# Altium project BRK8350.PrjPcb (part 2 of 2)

## Sheet Transceiver-M2.SchDoc: BRK8350 - M.2
size C; Author: Casey Smith; Organization: Opal Kelly; Address1: 13500 SW 72nd Ave STE 100; Address2: Portland, OR 97223; Address3: 217.391.3724; Address4: http://www.opalkelly.com; DocumentNumber: 6; Revision: 1; SheetNumber: 6; SheetTotal: 7
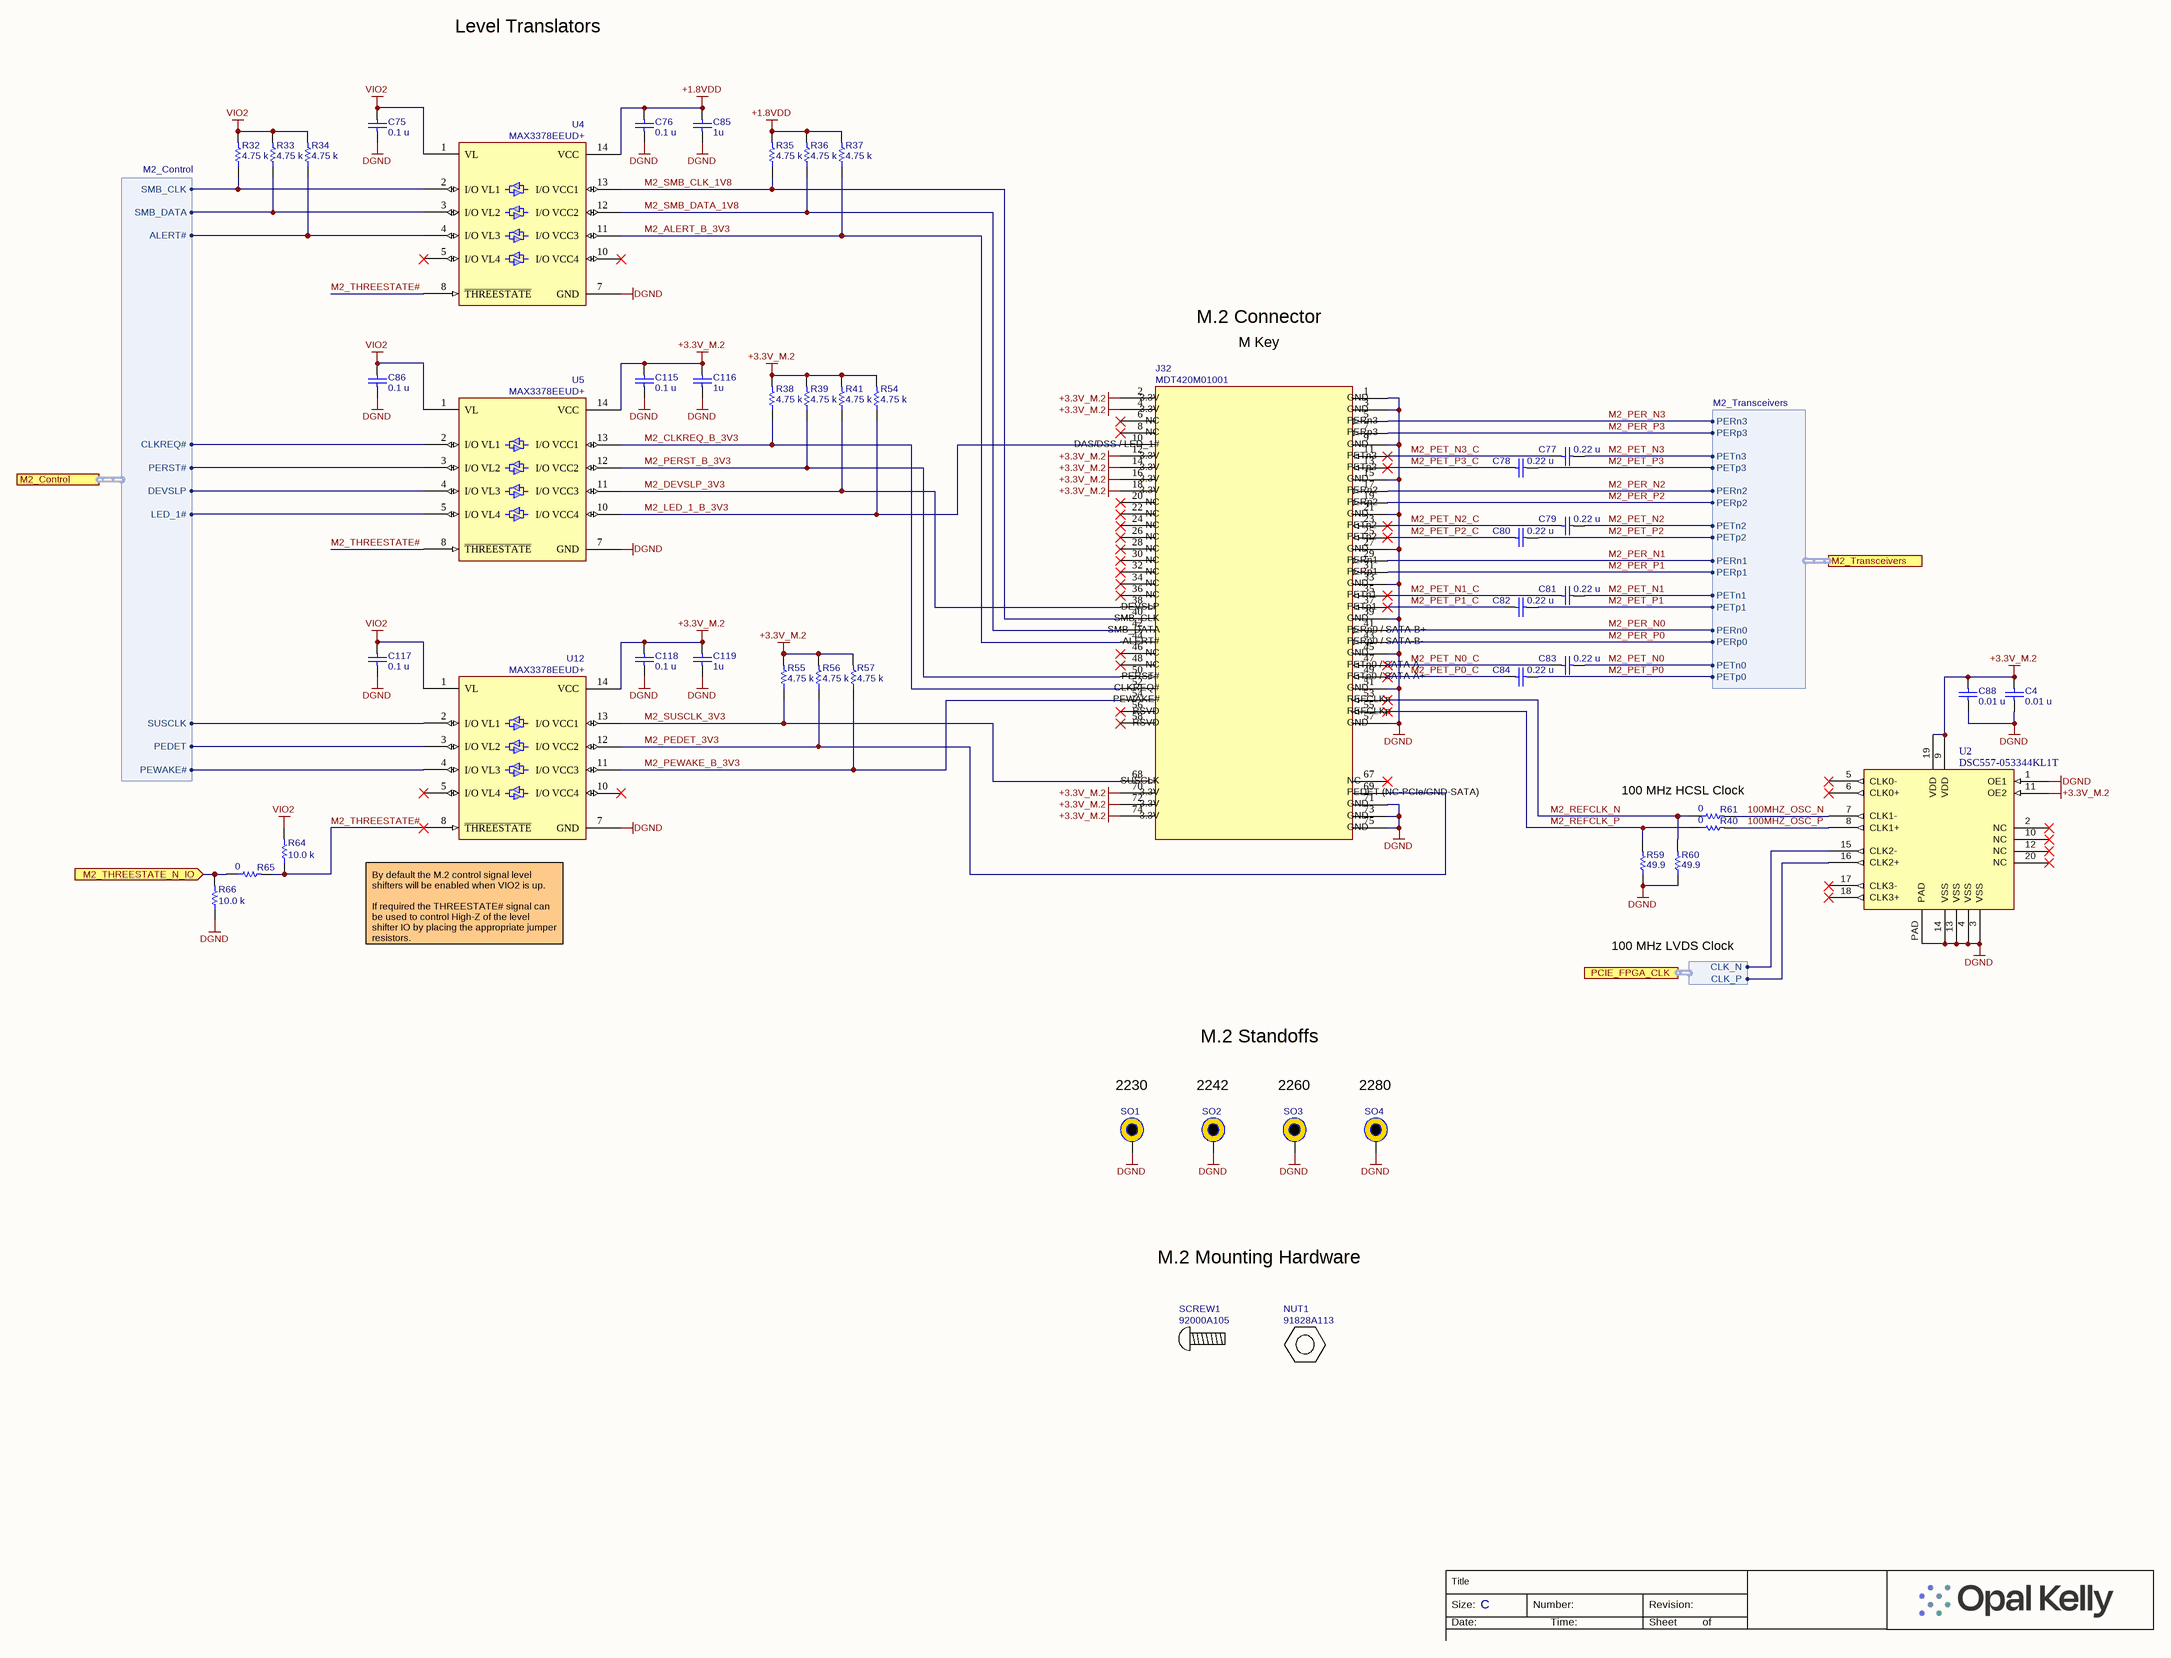
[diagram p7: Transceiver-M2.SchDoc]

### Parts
C4  value 0.01 u  [CAPC1005X06A]  (hidden comment: C0402C103K4RACTU)
C75  value 0.1 u  [CAPC1005X06A]  (hidden comment: C0402C104K8PACTU)
C76  value 0.1 u  [CAPC1005X06A]  (hidden comment: C0402C104K8PACTU)
C77  value 0.22 u  [CAPC1005X06A]  (hidden comment: SM-0402, 10%, 10V, X5R)
C78  value 0.22 u  [CAPC1005X06A]  (hidden comment: SM-0402, 10%, 10V, X5R)
C79  value 0.22 u  [CAPC1005X06A]  (hidden comment: SM-0402, 10%, 10V, X5R)
C80  value 0.22 u  [CAPC1005X06A]  (hidden comment: SM-0402, 10%, 10V, X5R)
C81  value 0.22 u  [CAPC1005X06A]  (hidden comment: SM-0402, 10%, 10V, X5R)
C82  value 0.22 u  [CAPC1005X06A]  (hidden comment: SM-0402, 10%, 10V, X5R)
C83  value 0.22 u  [CAPC1005X06A]  (hidden comment: SM-0402, 10%, 10V, X5R)
C84  value 0.22 u  [CAPC1005X06A]  (hidden comment: SM-0402, 10%, 10V, X5R)
C85  value 1u  [CAPC1005X06A]  (hidden comment: LMK105BJ105KV-F)
C86  value 0.1 u  [CAPC1005X06A]  (hidden comment: C0402C104K8PACTU)
C88  value 0.01 u  [CAPC1005X06A]  (hidden comment: C0402C103K4RACTU)
C115  value 0.1 u  [CAPC1005X06A]  (hidden comment: C0402C104K8PACTU)
C116  value 1u  [CAPC1005X06A]  (hidden comment: LMK105BJ105KV-F)
C117  value 0.1 u  [CAPC1005X06A]  (hidden comment: C0402C104K8PACTU)
C118  value 0.1 u  [CAPC1005X06A]  (hidden comment: C0402C104K8PACTU)
C119  value 1u  [CAPC1005X06A]  (hidden comment: LMK105BJ105KV-F)
J32  MDT420M01001  [M2-Connector_M-Keying]
NUT1  91828A113  (mechanical)
R32  value 4.75 k  [RESC1005X06A]  (hidden comment: CRCW04024K75FKED)
R33  value 4.75 k  [RESC1005X06A]  (hidden comment: CRCW04024K75FKED)
R34  value 4.75 k  [RESC1005X06A]  (hidden comment: CRCW04024K75FKED)
R35  value 4.75 k  [RESC1005X06A]  (hidden comment: CRCW04024K75FKED)
R36  value 4.75 k  [RESC1005X06A]  (hidden comment: CRCW04024K75FKED)
R37  value 4.75 k  [RESC1005X06A]  (hidden comment: CRCW04024K75FKED)
R38  value 4.75 k  [RESC1005X06A]  (hidden comment: CRCW04024K75FKED)
R39  value 4.75 k  [RESC1005X06A]  (hidden comment: CRCW04024K75FKED)
R40  value 0  [RESC1005X06A]  (hidden comment: SM-0402, 1%, 1/16W)
R41  value 4.75 k  [RESC1005X06A]  (hidden comment: CRCW04024K75FKED)
R54  value 4.75 k  [RESC1005X06A]  (hidden comment: CRCW04024K75FKED)
R55  value 4.75 k  [RESC1005X06A]  (hidden comment: CRCW04024K75FKED)
R56  value 4.75 k  [RESC1005X06A]  (hidden comment: CRCW04024K75FKED)
R57  value 4.75 k  [RESC1005X06A]  (hidden comment: CRCW04024K75FKED)
R59  value 49.9  [RESC1005X06A]  (hidden comment: SM-0402, 1%, 1/16W)
R60  value 49.9  [RESC1005X06A]  (hidden comment: SM-0402, 1%, 1/16W)
R61  value 0  [RESC1005X06A]  (hidden comment: SM-0402, 1%, 1/16W)
R64  value 10.0 k  [RESC1005X06A]  (hidden comment: CRCW040210K0FKED)
R65  value 0  [RESC1005X06A]  (hidden comment: SM-0402, 1%, 1/16W)
R66  value 10.0 k  [RESC1005X06A]  (hidden comment: CRCW040210K0FKED)
SCREW1  92000A105  (mechanical)
SO1  Standoff  [9774025151R-NO-PASTE]  (value not drawn)
SO2  Standoff  [9774025151R-NO-PASTE]  (value not drawn)
SO3  Standoff  [9774025151R-NO-PASTE]  (value not drawn)
SO4  Standoff  [9774025151R]  (value not drawn)
U2  DSC557-053344KL1T  [DSC557-05]
U4  MAX3378EEUD+  [MAX3378EEUD+]
U5  MAX3378EEUD+  [MAX3378EEUD+]
U12  MAX3378EEUD+  [MAX3378EEUD+]

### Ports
M2_Control (harness M2_Control), M2_THREESTATE_N_IO (in), M2_Transceivers (harness M2_Transceivers), PCIE_FPGA_CLK (harness CLK)

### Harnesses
M2_Control: DEVSLP, SMB_CLK, SMB_DATA, ALERT#, PERST#, CLKREQ#, PEWAKE#, LED_1#, SUSCLK, PEDET
M2_Transceivers: PETn3, PETp3, PERn3, PERp3, PETn2, PETp2, PERn2, PERp2, PETn1, PETp1, PERn1, PERp1, PETn0, PETp0, PERn0, PERp0
CLK: CLK_P, CLK_N

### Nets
+1.8VDD: C76.2 C85.2 R35.2 R36.2 R37.2 U4.14(VCC)
+3.3V_M.2: C4.2 C88.2 C115.2 C116.2 C118.2 C119.2 J32.2 J32.4 J32.12 J32.14 J32.16 J32.18 J32.70 J32.72 J32.74 R38.2 R39.2 R41.2 R54.2 R55.2 R56.2 R57.2 U2.9(VDD) U2.11(OE2) U2.19(VDD) U5.14(VCC) U12.14(VCC)
DGND: C4.1 C75.1 C76.1 C85.1 C86.1 C88.1 C115.1 C116.1 C117.1 C118.1 C119.1 J32.1 J32.3 J32.9 J32.15 J32.21 J32.27 J32.33 J32.39 J32.45 J32.51 J32.57 J32.71 J32.73 J32.75 R59.1 R60.1 R66.1 SO1.1 SO2.1 SO3.1 SO4.1 U2.1(OE1) U2.3(VSS) U2.4(VSS) U2.13(VSS) U2.14(VSS) U2.PAD U4.7(GND) U5.7(GND) U12.7(GND)
VIO2: C75.2 C86.2 C117.2 R32.2 R33.2 R34.2 R64.2 U4.1(VL) U5.1(VL) U12.1(VL)
100MHZ _REFCLK_P: U2.16(CLK2+) ; port PCIE_FPGA_CLK.CLK_P
100MHZ_OSC_N: R61.2 U2.7(CLK1-)
100MHZ_OSC_P: R40.2 U2.8(CLK1+)
100MHZ_REFCLK_N: U2.15(CLK2-) ; port PCIE_FPGA_CLK.CLK_N
M2_ALERT_B: R34.1 U4.4(I/O_VL3) ; port M2_Control.ALERT#
M2_ALERT_B_3V3: J32.44 R37.1 U4.11(I/O_VCC3)
M2_CLKREQ_B: U5.2(I/O_VL1) ; port M2_Control.CLKREQ#
M2_CLKREQ_B_3V3: J32.52 R38.1 U5.13(I/O_VCC1)
M2_DEVSLP: U5.4(I/O_VL3) ; port M2_Control.DEVSLP
M2_DEVSLP_3V3: J32.38 R41.1 U5.11(I/O_VCC3)
M2_LED_1_B: U5.5(I/O_VL4) ; port M2_Control.LED_1#
M2_LED_1_B_3V3: J32.10 R54.1 U5.10(I/O_VCC4)
M2_PEDET: U12.3(I/O_VL2) ; port M2_Control.PEDET
M2_PEDET_3V3: J32.69 R56.1 U12.12(I/O_VCC2)
M2_PER_N0: J32.41 ; port M2_Transceivers.PERn0
M2_PER_N1: J32.29 ; port M2_Transceivers.PERn1
M2_PER_N2: J32.17 ; port M2_Transceivers.PERn2
M2_PER_N3: J32.5 ; port M2_Transceivers.PERn3
M2_PER_P0: J32.43 ; port M2_Transceivers.PERp0
M2_PER_P1: J32.31 ; port M2_Transceivers.PERp1
M2_PER_P2: J32.19 ; port M2_Transceivers.PERp2
M2_PER_P3: J32.7 ; port M2_Transceivers.PERp3
M2_PERST_B: U5.3(I/O_VL2) ; port M2_Control.PERST#
M2_PERST_B_3V3: J32.50 R39.1 U5.12(I/O_VCC2)
M2_PET_N0: C83.1 ; port M2_Transceivers.PETn0
M2_PET_N0_C: C83.2 J32.47
M2_PET_N1: C81.1 ; port M2_Transceivers.PETn1
M2_PET_N1_C: C81.2 J32.35
M2_PET_N2: C79.1 ; port M2_Transceivers.PETn2
M2_PET_N2_C: C79.2 J32.23
M2_PET_N3: C77.1 ; port M2_Transceivers.PETn3
M2_PET_N3_C: C77.2 J32.11
M2_PET_P0: C84.1 ; port M2_Transceivers.PETp0
M2_PET_P0_C: C84.2 J32.49
M2_PET_P1: C82.1 ; port M2_Transceivers.PETp1
M2_PET_P1_C: C82.2 J32.37
M2_PET_P2: C80.1 ; port M2_Transceivers.PETp2
M2_PET_P2_C: C80.2 J32.25
M2_PET_P3: C78.1 ; port M2_Transceivers.PETp3
M2_PET_P3_C: C78.2 J32.13
M2_PEWAKE_B: U12.4(I/O_VL3) ; port M2_Control.PEWAKE#
M2_PEWAKE_B_3V3: J32.54 R57.1 U12.11(I/O_VCC3)
M2_REFCLK_N: J32.53 R60.2 R61.1
M2_REFCLK_P: J32.55 R40.1 R59.2
M2_SMB_CLK: R32.1 U4.2(I/O_VL1) ; port M2_Control.SMB_CLK
M2_SMB_CLK_1V8: J32.40 R35.1 U4.13(I/O_VCC1)
M2_SMB_DATA: R33.1 U4.3(I/O_VL2) ; port M2_Control.SMB_DATA
M2_SMB_DATA_1V8: J32.42 R36.1 U4.12(I/O_VCC2)
M2_SUSCLK: U12.2(I/O_VL1) ; port M2_Control.SUSCLK
M2_SUSCLK_3V3: J32.68 R55.1 U12.13(I/O_VCC1)
M2_THREESTATE#: R64.1 R65.2 U4.8(~{THREESTATE}) U5.8(~{THREESTATE}) U12.8(~{THREESTATE})
M2_THREESTATE_N_IO: R65.1 R66.2 ; port M2_THREESTATE_N_IO

Not connected (* = marked no-connect by the designer): J32 6* 8* 20* 22* 24* 26* 28* 30* 32* 34* 36* 46* 48* 56* 58* 67*; U2 2(NC)* 5(CLK0-)* 6(CLK0+)* 10(NC)* 12(NC)* 17(CLK3-)* 18(CLK3+)* 20(NC)*; U4 5(I/O_VL4)* 10(I/O_VCC4)*; U12 5(I/O_VL4)* 10(I/O_VCC4)*

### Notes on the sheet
- Level Translators
- M.2 Connector
- M Key
- 100 MHz HCSL Clock
- (near U12) By default the M.2 control signal level shifters will be enabled when VIO2 is up.
  If required the THREESTATE# signal can be used to control High-Z of the level shifter IO by placing the appropriate jumper resistors.
- 100 MHz LVDS Clock
- M.2 Standoffs
- 2230
- 2242
- 2260
- 2280
- M.2 Mounting Hardware
- Title
- Size:
- Date:
- C
- Number:
- Time:
- Revision:
- Sheet
- of

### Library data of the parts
C4 C88 = 000295: Ceramic Capacitor; Partnumber: 000295; Manufacturer: Kemet; ValueFloat: 1E-8; Tolerance (%): 10; Description 2: SM-0402, 10%, 16V, X5R
C75 C76 C86 C115 C117 C118 = 000070: Partnumber: 000070; manufacturer: Kemet; ValueFloat: 1E-7; x_tolerance: 10
C77-C84 = 000333: Partnumber: 000333; manufacturer: Taiyo Yuden; manufacturer_pn: LMK105BJ224KV-F; ValueFloat: 2.2E-7; id: 3750; inventory_price: 0.0056; reorder_quantity: 10000; x_tolerance: 10
C85 C116 C119 = 000480: Partnumber: 000480; manufacturer: Taiyo Yuden; ValueFloat: 1E-6; x_tolerance: 10
J32 = 001722: Partnumber: 001722; manufacturer: Amphenol; id: 221876; inventory_price: 0.75
NUT1 = NUT: M2.5 hex nut; Manufacturer: McMaster-Carr; partnumber: 001810
R32-R39 R41 R54-R57 = 001008: Partnumber: 001008; manufacturer: Vishay; ValueFloat: 4750; x_tolerance: 1
R40 R61 R65 = 001713: Partnumber: 001713; manufacturer: Vishay; manufacturer_pn: CRCW04020000Z0EDC; id: 219362; inventory_price: 0.004; reorder_quantity: 20000; x_tolerance: 1
R59 R60 = 001715: Partnumber: 001715; manufacturer: Vishay; manufacturer_pn: CRCW040249R9FKEDC; id: 219364; inventory_price: 0.005; reorder_quantity: 1000; x_tolerance: 1
R64 R66 = 001521: Thick-film resistor; Manufacturer: Vishay; partnumber: 001521; Description 2: SM-0402, 1%, 1/16W; ValueFloat: 10000; Tolerance (%): 1; x_lifecycle_status: Production
SCREW1 = SCREW: Metric Pan Head Phil Machine Screw; Manufacturer: McMaster-Carr; partnumber: 001811
SO1-SO4 = 9774025151R: SMT steel standoff, M2.5 threads, 2.5 mm stack height; Manufacturer: Wurth; partnumber: 001726
U2 = 002422: Crystal-less Four Output PCIe Clock Generator; Partnumber: 002422; Manufacturer: Microchip; Description 2: 2xHCSL 2xLVDS 100Mhz
U4 U5 U12 = 000178: Partnumber: 000178; manufacturer: Maxim

## Sheet MC3-Transceiver.SchDoc: BRK8350 - Mezzanine Connector MC3
size C; Author: Casey Smith; Organization: Opal Kelly; Address1: 13500 SW 72nd Ave STE 100; Address2: Portland, OR 97223; Address3: 217.391.3724; Address4: http://www.opalkelly.com; DocumentNumber: 4; Revision: 1; SheetNumber: 4; SheetTotal: 7
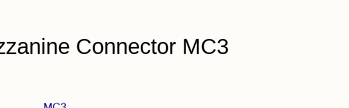
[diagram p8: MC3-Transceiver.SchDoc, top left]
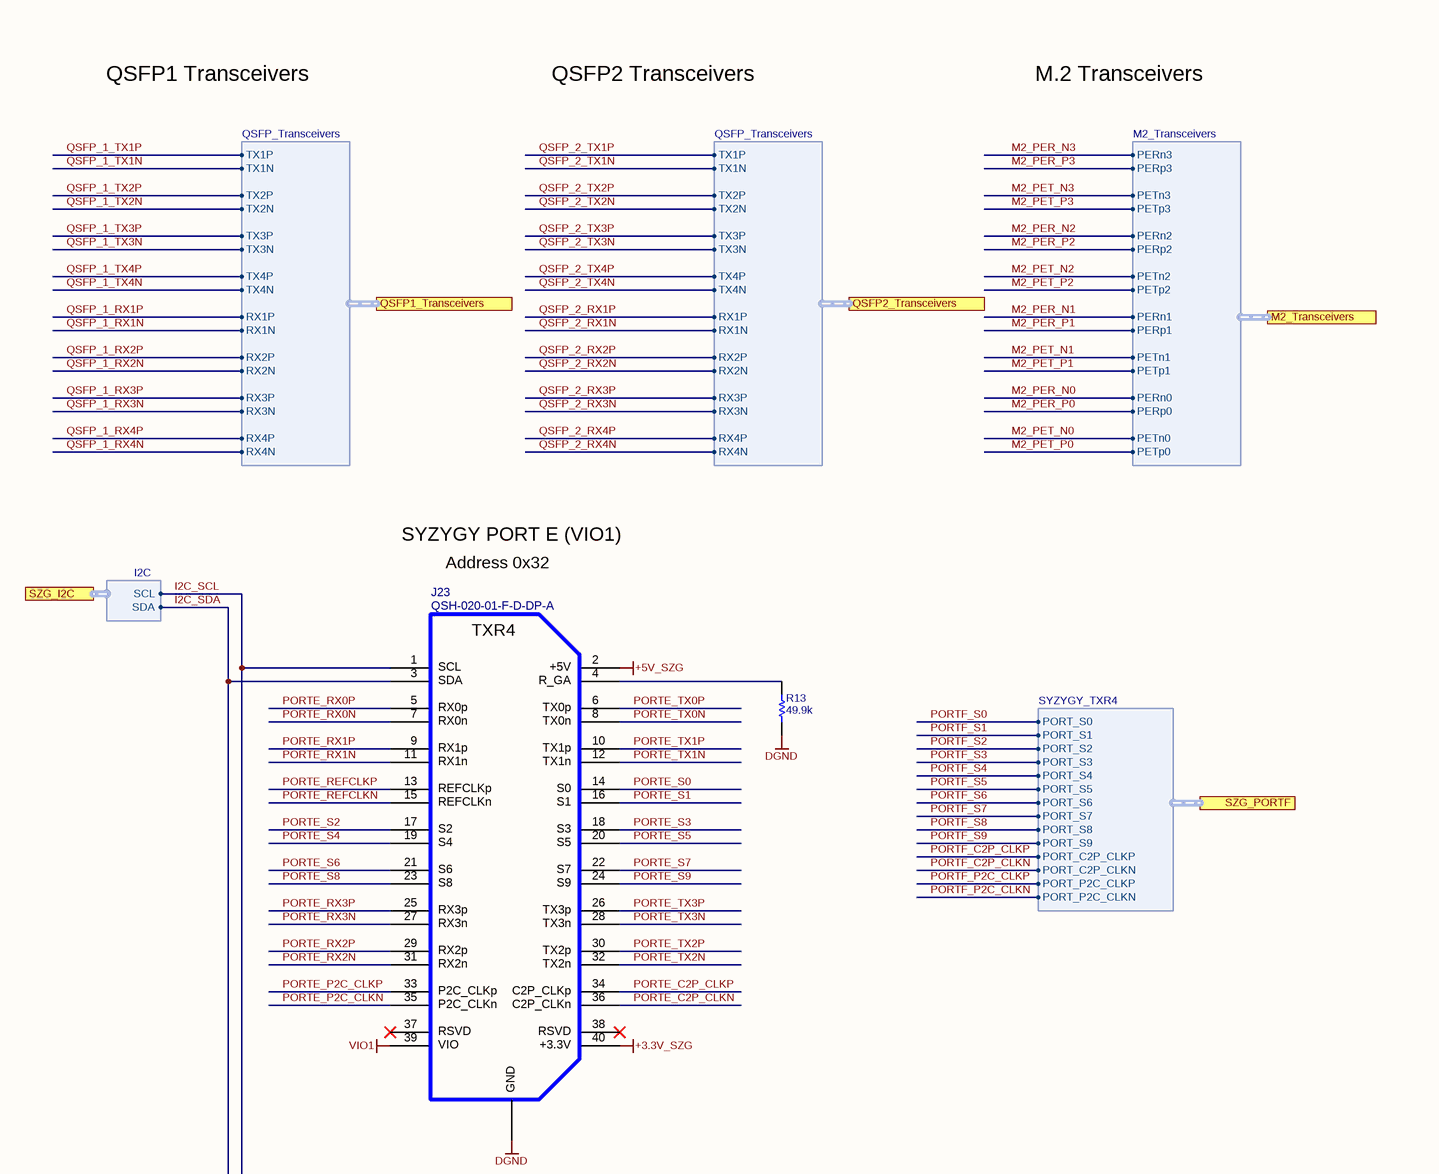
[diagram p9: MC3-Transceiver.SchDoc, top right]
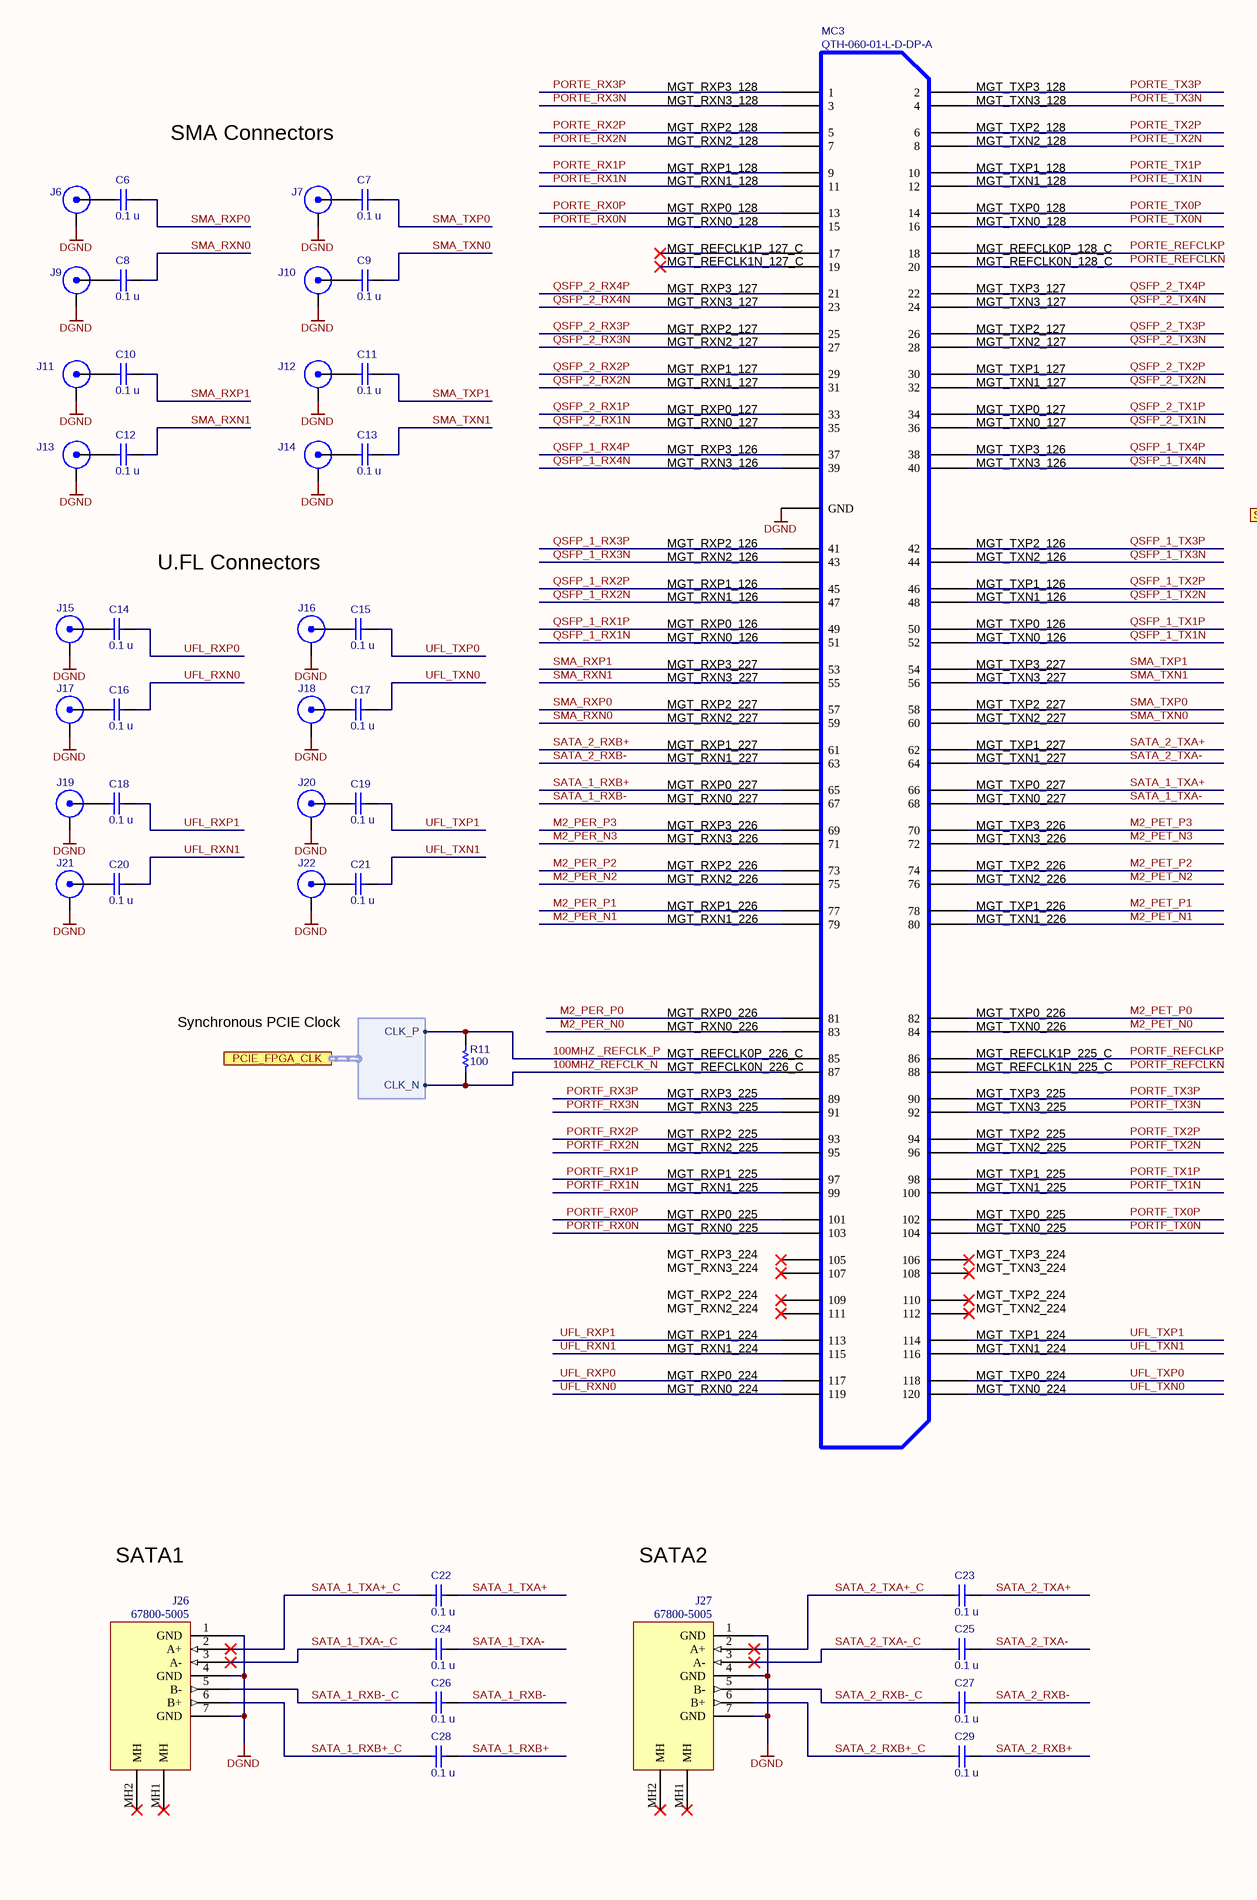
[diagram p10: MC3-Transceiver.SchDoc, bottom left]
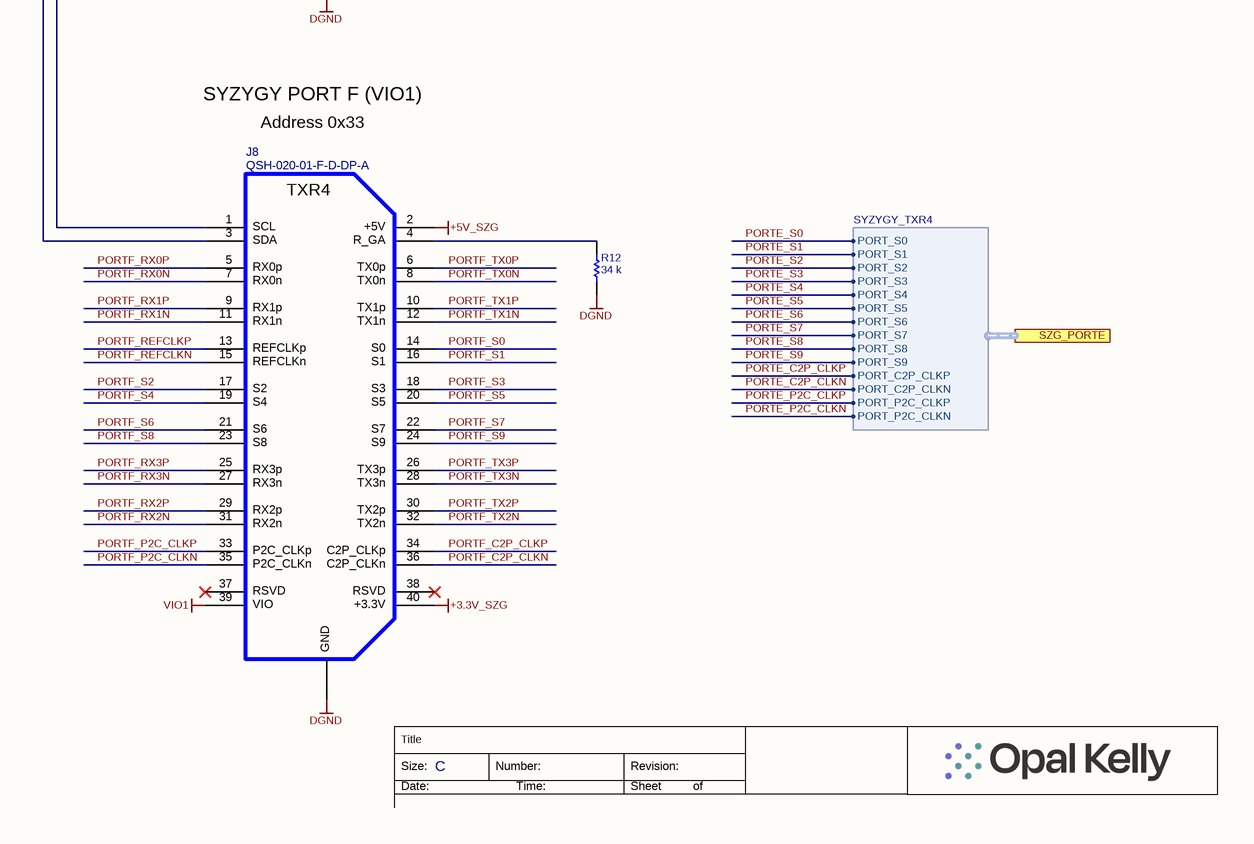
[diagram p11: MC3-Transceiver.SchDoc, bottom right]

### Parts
C6  value 0.1 u  [CAPC1005X06A]  (hidden comment: SM-0402, 10%, 10v)
C7  value 0.1 u  [CAPC1005X06A]  (hidden comment: SM-0402, 10%, 10v)
C8  value 0.1 u  [CAPC1005X06A]  (hidden comment: SM-0402, 10%, 10v)
C9  value 0.1 u  [CAPC1005X06A]  (hidden comment: SM-0402, 10%, 10v)
C10  value 0.1 u  [CAPC1005X06A]  (hidden comment: SM-0402, 10%, 10v)
C11  value 0.1 u  [CAPC1005X06A]  (hidden comment: SM-0402, 10%, 10v)
C12  value 0.1 u  [CAPC1005X06A]  (hidden comment: SM-0402, 10%, 10v)
C13  value 0.1 u  [CAPC1005X06A]  (hidden comment: SM-0402, 10%, 10v)
C14  value 0.1 u  [CAPC1005X06A]  (hidden comment: SM-0402, 10%, 10v)
C15  value 0.1 u  [CAPC1005X06A]  (hidden comment: SM-0402, 10%, 10v)
C16  value 0.1 u  [CAPC1005X06A]  (hidden comment: SM-0402, 10%, 10v)
C17  value 0.1 u  [CAPC1005X06A]  (hidden comment: SM-0402, 10%, 10v)
C18  value 0.1 u  [CAPC1005X06A]  (hidden comment: SM-0402, 10%, 10v)
C19  value 0.1 u  [CAPC1005X06A]  (hidden comment: SM-0402, 10%, 10v)
C20  value 0.1 u  [CAPC1005X06A]  (hidden comment: SM-0402, 10%, 10v)
C21  value 0.1 u  [CAPC1005X06A]  (hidden comment: SM-0402, 10%, 10v)
C22  value 0.1 u  [CAPC1005X06A]  (hidden comment: SM-0402, 10%, 10v)
C23  value 0.1 u  [CAPC1005X06A]  (hidden comment: SM-0402, 10%, 10v)
C24  value 0.1 u  [CAPC1005X06A]  (hidden comment: SM-0402, 10%, 10v)
C25  value 0.1 u  [CAPC1005X06A]  (hidden comment: SM-0402, 10%, 10v)
C26  value 0.1 u  [CAPC1005X06A]  (hidden comment: SM-0402, 10%, 10v)
C27  value 0.1 u  [CAPC1005X06A]  (hidden comment: SM-0402, 10%, 10v)
C28  value 0.1 u  [CAPC1005X06A]  (hidden comment: SM-0402, 10%, 10v)
C29  value 0.1 u  [CAPC1005X06A]  (hidden comment: SM-0402, 10%, 10v)
J6  RXP0  [SMA]  (value not drawn)
J7  TXP0  [SMA]  (value not drawn)
J8  QSH-020-01-F-D-DP-A  [QSH-020-01-X-D-DP-A-L-SYZYGY]
J9  RXN0  [SMA]  (value not drawn)
J10  TXN0  [SMA]  (value not drawn)
J11  RXP1  [SMA]  (value not drawn)
J12  TXP1  [SMA]  (value not drawn)
J13  RXN1  [SMA]  (value not drawn)
J14  TXN1  [SMA]  (value not drawn)
J15  RXP0  [UFL-R-SMT-1]  (value not drawn)
J16  TXP0  [UFL-R-SMT-1]  (value not drawn)
J17  RXN0  [UFL-R-SMT-1]  (value not drawn)
J18  TXN0  [UFL-R-SMT-1]  (value not drawn)
J19  RXP1  [UFL-R-SMT-1]  (value not drawn)
J20  TXP1  [UFL-R-SMT-1]  (value not drawn)
J21  RXN1  [UFL-R-SMT-1]  (value not drawn)
J22  TXN1  [UFL-R-SMT-1]  (value not drawn)
J23  QSH-020-01-F-D-DP-A  [QSH-020-01-X-D-DP-A-L-SYZYGY]
J26  67800-5005  [MOLEX-67800-5005]
J27  67800-5005  [MOLEX-67800-5005]
MC3  QTH-060-01-L-D-DP-A  [QTH-060-01-X-D-DP-A]
R11  value 100  [RESC1005X06A]  (hidden comment: SM-0402, 1%, 1/16W)
R12  value 34 k  [RESC1005X06A]  (hidden comment: CRCW040234K0FKED)
R13  value 49.9k  [RESC1005X06A]  (hidden comment: CRCW040249K9FKED)

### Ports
M2_Transceivers (harness M2_Transceivers), PCIE_FPGA_CLK (harness CLK), QSFP1_Transceivers (harness QSFP_Transceivers), QSFP2_Transceivers (harness QSFP_Transceivers), SZG_I2C (harness I2C), SZG_PORTE (harness SYZYGY_TXR4), SZG_PORTF (harness SYZYGY_TXR4)

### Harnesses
QSFP_Transceivers: TX1P, TX1N, TX2P, TX2N, TX3P, TX3N, TX4P, TX4N, RX1P, RX1N, RX2P, RX2N, RX3P, RX3N, RX4P, RX4N
I2C: SCL, SDA
SYZYGY_TXR4: PORT_S0, PORT_S1, PORT_S2, PORT_S3, PORT_S4, PORT_S5, PORT_S6, PORT_S7, PORT_S8, PORT_S9, PORT_C2P_CLKP, PORT_C2P_CLKN, PORT_P2C_CLKP, PORT_P2C_CLKN
M2_Transceivers: PETn3, PETp3, PERn3, PERp3, PETn2, PETp2, PERn2, PERp2, PETn1, PETp1, PERn1, PERp1, PETn0, PETp0, PERn0, PERp0
CLK: CLK_P, CLK_N

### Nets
+3.3V_SZG: J8.40 J23.40
+5V_SZG: J8.2 J23.2
DGND: J6.2(GND) J7.2(GND) J8.0(GND) J9.2(GND) J10.2(GND) J11.2(GND) J12.2(GND) J13.2(GND) J14.2(GND) J15.2(GND) J16.2(GND) J17.2(GND) J18.2(GND) J19.2(GND) J20.2(GND) J21.2(GND) J22.2(GND) J23.0(GND) J26.1(GND) J26.4(GND) J26.7(GND) J27.1(GND) J27.4(GND) J27.7(GND) MC3.0(GND) R12.1 R13.1
VIO1: J8.39 J23.39
100MHZ _REFCLK_P: MC3.85 R11.2 ; port PCIE_FPGA_CLK.CLK_P
100MHZ_REFCLK_N: MC3.87 R11.1 ; port PCIE_FPGA_CLK.CLK_N
I2C_SCL: J8.1 J23.1 ; port SZG_I2C.SCL
I2C_SDA: J8.3 J23.3 ; port SZG_I2C.SDA
M2_PER_N0: MC3.83 ; port M2_Transceivers.PERn0
M2_PER_N1: MC3.79 ; port M2_Transceivers.PERn1
M2_PER_N2: MC3.75 ; port M2_Transceivers.PERn2
M2_PER_N3: MC3.71 ; port M2_Transceivers.PERn3
M2_PER_P0: MC3.81 ; port M2_Transceivers.PERp0
M2_PER_P1: MC3.77 ; port M2_Transceivers.PERp1
M2_PER_P2: MC3.73 ; port M2_Transceivers.PERp2
M2_PER_P3: MC3.69 ; port M2_Transceivers.PERp3
M2_PET_N0: MC3.84 ; port M2_Transceivers.PETn0
M2_PET_N1: MC3.80 ; port M2_Transceivers.PETn1
M2_PET_N2: MC3.76 ; port M2_Transceivers.PETn2
M2_PET_N3: MC3.72 ; port M2_Transceivers.PETn3
M2_PET_P0: MC3.82 ; port M2_Transceivers.PETp0
M2_PET_P1: MC3.78 ; port M2_Transceivers.PETp1
M2_PET_P2: MC3.74 ; port M2_Transceivers.PETp2
M2_PET_P3: MC3.70 ; port M2_Transceivers.PETp3
PORTE_C2P_CLKN: J23.36 ; port SZG_PORTE.PORT_C2P_CLKN
PORTE_C2P_CLKP: J23.34 ; port SZG_PORTE.PORT_C2P_CLKP
PORTE_P2C_CLKN: J23.35 ; port SZG_PORTE.PORT_P2C_CLKN
PORTE_P2C_CLKP: J23.33 ; port SZG_PORTE.PORT_P2C_CLKP
PORTE_REFCLKN: J23.15 MC3.20
PORTE_REFCLKP: J23.13 MC3.18
PORTE_RX0N: J23.7 MC3.15
PORTE_RX0P: J23.5 MC3.13
PORTE_RX1N: J23.11 MC3.11
PORTE_RX1P: J23.9 MC3.9
PORTE_RX2N: J23.31 MC3.7
PORTE_RX2P: J23.29 MC3.5
PORTE_RX3N: J23.27 MC3.3
PORTE_RX3P: J23.25 MC3.1
PORTE_S0: J23.14 ; port SZG_PORTE.PORT_S0
PORTE_S1: J23.16 ; port SZG_PORTE.PORT_S1
PORTE_S2: J23.17 ; port SZG_PORTE.PORT_S2
PORTE_S3: J23.18 ; port SZG_PORTE.PORT_S3
PORTE_S4: J23.19 ; port SZG_PORTE.PORT_S4
PORTE_S5: J23.20 ; port SZG_PORTE.PORT_S5
PORTE_S6: J23.21 ; port SZG_PORTE.PORT_S6
PORTE_S7: J23.22 ; port SZG_PORTE.PORT_S7
PORTE_S8: J23.23 ; port SZG_PORTE.PORT_S8
PORTE_S9: J23.24 ; port SZG_PORTE.PORT_S9
PORTE_TX0N: J23.8 MC3.16
PORTE_TX0P: J23.6 MC3.14
PORTE_TX1N: J23.12 MC3.12
PORTE_TX1P: J23.10 MC3.10
PORTE_TX2N: J23.32 MC3.8
PORTE_TX2P: J23.30 MC3.6
PORTE_TX3N: J23.28 MC3.4
PORTE_TX3P: J23.26 MC3.2
PORTF_C2P_CLKN: J8.36 ; port SZG_PORTF.PORT_C2P_CLKN
PORTF_C2P_CLKP: J8.34 ; port SZG_PORTF.PORT_C2P_CLKP
PORTF_P2C_CLKN: J8.35 ; port SZG_PORTF.PORT_P2C_CLKN
PORTF_P2C_CLKP: J8.33 ; port SZG_PORTF.PORT_P2C_CLKP
PORTF_REFCLKN: J8.15 MC3.88
PORTF_REFCLKP: J8.13 MC3.86
PORTF_RX0N: J8.7 MC3.103
PORTF_RX0P: J8.5 MC3.101
PORTF_RX1N: J8.11 MC3.99
PORTF_RX1P: J8.9 MC3.97
PORTF_RX2N: J8.31 MC3.95
PORTF_RX2P: J8.29 MC3.93
PORTF_RX3N: J8.27 MC3.91
PORTF_RX3P: J8.25 MC3.89
PORTF_S0: J8.14 ; port SZG_PORTF.PORT_S0
PORTF_S1: J8.16 ; port SZG_PORTF.PORT_S1
PORTF_S2: J8.17 ; port SZG_PORTF.PORT_S2
PORTF_S3: J8.18 ; port SZG_PORTF.PORT_S3
PORTF_S4: J8.19 ; port SZG_PORTF.PORT_S4
PORTF_S5: J8.20 ; port SZG_PORTF.PORT_S5
PORTF_S6: J8.21 ; port SZG_PORTF.PORT_S6
PORTF_S7: J8.22 ; port SZG_PORTF.PORT_S7
PORTF_S8: J8.23 ; port SZG_PORTF.PORT_S8
PORTF_S9: J8.24 ; port SZG_PORTF.PORT_S9
PORTF_TX0N: J8.8 MC3.104
PORTF_TX0P: J8.6 MC3.102
PORTF_TX1N: J8.12 MC3.100
PORTF_TX1P: J8.10 MC3.98
PORTF_TX2N: J8.32 MC3.96
PORTF_TX2P: J8.30 MC3.94
PORTF_TX3N: J8.28 MC3.92
PORTF_TX3P: J8.26 MC3.90
QSFP_1_RX1N: MC3.51 ; port QSFP1_Transceivers.RX1N
QSFP_1_RX1P: MC3.49 ; port QSFP1_Transceivers.RX1P
QSFP_1_RX2N: MC3.47 ; port QSFP1_Transceivers.RX2N
QSFP_1_RX2P: MC3.45 ; port QSFP1_Transceivers.RX2P
QSFP_1_RX3N: MC3.43 ; port QSFP1_Transceivers.RX3N
QSFP_1_RX3P: MC3.41 ; port QSFP1_Transceivers.RX3P
QSFP_1_RX4N: MC3.39 ; port QSFP1_Transceivers.RX4N
QSFP_1_RX4P: MC3.37 ; port QSFP1_Transceivers.RX4P
QSFP_1_TX1N: MC3.52 ; port QSFP1_Transceivers.TX1N
QSFP_1_TX1P: MC3.50 ; port QSFP1_Transceivers.TX1P
QSFP_1_TX2N: MC3.48 ; port QSFP1_Transceivers.TX2N
QSFP_1_TX2P: MC3.46 ; port QSFP1_Transceivers.TX2P
QSFP_1_TX3N: MC3.44 ; port QSFP1_Transceivers.TX3N
QSFP_1_TX3P: MC3.42 ; port QSFP1_Transceivers.TX3P
QSFP_1_TX4N: MC3.40 ; port QSFP1_Transceivers.TX4N
QSFP_1_TX4P: MC3.38 ; port QSFP1_Transceivers.TX4P
QSFP_2_RX1N: MC3.35 ; port QSFP2_Transceivers.RX1N
QSFP_2_RX1P: MC3.33 ; port QSFP2_Transceivers.RX1P
QSFP_2_RX2N: MC3.31 ; port QSFP2_Transceivers.RX2N
QSFP_2_RX2P: MC3.29 ; port QSFP2_Transceivers.RX2P
QSFP_2_RX3N: MC3.27 ; port QSFP2_Transceivers.RX3N
QSFP_2_RX3P: MC3.25 ; port QSFP2_Transceivers.RX3P
QSFP_2_RX4N: MC3.23 ; port QSFP2_Transceivers.RX4N
QSFP_2_RX4P: MC3.21 ; port QSFP2_Transceivers.RX4P
QSFP_2_TX1N: MC3.36 ; port QSFP2_Transceivers.TX1N
QSFP_2_TX1P: MC3.34 ; port QSFP2_Transceivers.TX1P
QSFP_2_TX2N: MC3.32 ; port QSFP2_Transceivers.TX2N
QSFP_2_TX2P: MC3.30 ; port QSFP2_Transceivers.TX2P
QSFP_2_TX3N: MC3.28 ; port QSFP2_Transceivers.TX3N
QSFP_2_TX3P: MC3.26 ; port QSFP2_Transceivers.TX3P
QSFP_2_TX4N: MC3.24 ; port QSFP2_Transceivers.TX4N
QSFP_2_TX4P: MC3.22 ; port QSFP2_Transceivers.TX4P
SATA_1_RXB+: C28.2 MC3.65
SATA_1_RXB+_C: C28.1 J26.6(B+)
SATA_1_RXB-: C26.2 MC3.67
SATA_1_RXB-_C: C26.1 J26.5(B-)
SATA_1_TXA+: C22.2 MC3.66
SATA_1_TXA+_C: C22.1 J26.2(A+)
SATA_1_TXA-: C24.2 MC3.68
SATA_1_TXA-_C: C24.1 J26.3(A-)
SATA_2_RXB+: C29.2 MC3.61
SATA_2_RXB+_C: C29.1 J27.6(B+)
SATA_2_RXB-: C27.2 MC3.63
SATA_2_RXB-_C: C27.1 J27.5(B-)
SATA_2_TXA+: C23.2 MC3.62
SATA_2_TXA+_C: C23.1 J27.2(A+)
SATA_2_TXA-: C25.2 MC3.64
SATA_2_TXA-_C: C25.1 J27.3(A-)
SMA_RXN0: C8.2 MC3.59
SMA_RXN1: C12.2 MC3.55
SMA_RXP0: C6.2 MC3.57
SMA_RXP1: C10.2 MC3.53
SMA_TXN0: C9.2 MC3.60
SMA_TXN1: C13.2 MC3.56
SMA_TXP0: C7.2 MC3.58
SMA_TXP1: C11.2 MC3.54
UFL_RXN0: C16.2 MC3.119
UFL_RXN1: C20.2 MC3.115
UFL_RXP0: C14.2 MC3.117
UFL_RXP1: C18.2 MC3.113
UFL_TXN0: C17.2 MC3.120
UFL_TXN1: C21.2 MC3.116
UFL_TXP0: C15.2 MC3.118
UFL_TXP1: C19.2 MC3.114
NetC6_1: C6.1 J6.1(SIGNAL)
NetC7_1: C7.1 J7.1(SIGNAL)
NetC8_1: C8.1 J9.1(SIGNAL)
NetC9_1: C9.1 J10.1(SIGNAL)
NetC10_1: C10.1 J11.1(SIGNAL)
NetC11_1: C11.1 J12.1(SIGNAL)
NetC12_1: C12.1 J13.1(SIGNAL)
NetC13_1: C13.1 J14.1(SIGNAL)
NetC14_1: C14.1 J15.1(SIGNAL)
NetC15_1: C15.1 J16.1(SIGNAL)
NetC16_1: C16.1 J17.1(SIGNAL)
NetC17_1: C17.1 J18.1(SIGNAL)
NetC18_1: C18.1 J19.1(SIGNAL)
NetC19_1: C19.1 J20.1(SIGNAL)
NetC20_1: C20.1 J21.1(SIGNAL)
NetC21_1: C21.1 J22.1(SIGNAL)
NetJ8_4: J8.4 R12.2
NetJ23_4: J23.4 R13.2

Not connected (* = marked no-connect by the designer): J8 37* 38*; J23 37* 38*; J26 MH1(MH)* MH2(MH)*; J27 MH1(MH)* MH2(MH)*; MC3 17* 19* 105* 106* 107* 108* 109* 110* 111* 112*

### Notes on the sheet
- Mezzanine Connector MC3
- QSFP1 Transceivers
- QSFP2 Transceivers
- M.2 Transceivers
- SMA Connectors
- Address 0x32
- SYZYGY PORT E (VIO1)
- U.FL Connectors
- Synchronous PCIE Clock
- SYZYGY PORT F (VIO1)
- Address 0x33
- (near MC3) MGT_RXP3_128
  MGT_RXN3_128
  MGT_RXP2_128
  MGT_RXN2_128
  MGT_RXP1_128
  MGT_RXN1_128
  MGT_RXP0_128
  MGT_RXN0_128
  MGT_REFCLK1P_127_C
  MGT_REFCLK1N_127_C
  MGT_RXP3_127
  MGT_RXN3_127
  MGT_RXP2_127
  MGT_RXN2_127
  MGT_RXP1_127
  MGT_RXN1_127
  MGT_RXP0_127
  MGT_RXN0_127
  MGT_RXP3_126
  MGT_RXN3_126
  MGT_RXP2_126
  MGT_RXN2_126
  MGT_RXP1_126
  MGT_RXN1_126
  MGT_RXP0_126
  MGT_RXN0_126
  MGT_RXP3_227
  MGT_RXN3_227
  MGT_RXP2_227
  MGT_RXN2_227
  MGT_RXP1_227
  MGT_RXN1_227
  MGT_RXP0_227
  MGT_RXN0_227
  MGT_RXP3_226
  MGT_RXN3_226
  MGT_RXP2_226
  MGT_RXN2_226
  MGT_RXP1_226
  MGT_RXN1_226
  MGT_RXP0_226
  MGT_RXN0_226
  MGT_REFCLK0P_226_C
  MGT_REFCLK0N_226_C
  MGT_RXP3_225
  MGT_RXN3_225
  MGT_RXP2_225
  MGT_RXN2_225
  MGT_RXP1_225
  MGT_RXN1_225
  MGT_RXP0_225
  MGT_RXN0_225
  MGT_RXP3_224
  MGT_RXN3_224
  MGT_RXP2_224
  MGT_RXN2_224
  MGT_RXP1_224
  MGT_RXN1_224
  MGT_RXP0_224
  MGT_RXN0_224
- (near MC3) MGT_TXP3_128
  MGT_TXN3_128
  MGT_TXP2_128
  MGT_TXN2_128
  MGT_TXP1_128
  MGT_TXN1_128
  MGT_TXP0_128
  MGT_TXN0_128
  MGT_REFCLK0P_128_C
  MGT_REFCLK0N_128_C
  MGT_TXP3_127
  MGT_TXN3_127
  MGT_TXP2_127
  MGT_TXN2_127
  MGT_TXP1_127
  MGT_TXN1_127
  MGT_TXP0_127
  MGT_TXN0_127
  MGT_TXP3_126
  MGT_TXN3_126
  MGT_TXP2_126
  MGT_TXN2_126
  MGT_TXP1_126
  MGT_TXN1_126
  MGT_TXP0_126
  MGT_TXN0_126
  MGT_TXP3_227
  MGT_TXN3_227
  MGT_TXP2_227
  MGT_TXN2_227
  MGT_TXP1_227
  MGT_TXN1_227
  MGT_TXP0_227
  MGT_TXN0_227
  MGT_TXP3_226
  MGT_TXN3_226
  MGT_TXP2_226
  MGT_TXN2_226
  MGT_TXP1_226
  MGT_TXN1_226
  MGT_TXP0_226
  MGT_TXN0_226
  MGT_REFCLK1P_225_C
  MGT_REFCLK1N_225_C
  MGT_TXP3_225
  MGT_TXN3_225
  MGT_TXP2_225
  MGT_TXN2_225
  MGT_TXP1_225
  MGT_TXN1_225
  MGT_TXP0_225
  MGT_TXN0_225
  MGT_TXP3_224
  MGT_TXN3_224
  MGT_TXP2_224
  MGT_TXN2_224
  MGT_TXP1_224
  MGT_TXN1_224
  MGT_TXP0_224
  MGT_TXN0_224
- SATA1
- SATA2
- Title
- Size:
- Date:
- C
- Number:
- Time:
- Revision:
- Sheet
- of

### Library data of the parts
C6-C29 = 000070: Partnumber: 000070; manufacturer: Kemet; manufacturer_pn: C0402C104K8PACTU; ValueFloat: 1E-7; id: 750; inventory_price: 0.0023; reorder_quantity: 70000; x_tolerance: 10
J6 J7 J9-J14 = 000974: Straight SMA PCB Mount; Manufacturer: Amphenol; Manufacturer_PN: 901-144-8RFX; partnumber: 000974
J8 J23 = 000694: 0.5mm Double Row High Speed Socket Assembly; Partnumber: 000694; manufacturer: Samtec
J15-J22 = 001335: U.FL surface-mount coaxial connector; Manufacturer: Hirose; Manufacturer_PN: U.FL-R-SMT-1; partnumber: 001335; x_lifecycle_status: Production
J26 J27 = 000988: SATA 7-pin receptacle; Partnumber: 000988; Manufacturer: Molex; Description 2: Vertical Mount, SMD, Latch, 15u Gold
MC3 = 001769: Partnumber: 001769; manufacturer: Samtec
R11 = 000827: Partnumber: 000827; manufacturer: Vishay; manufacturer_pn: CRCW0402100RFKED; id: 13742; inventory_price: 0.0016; reorder_quantity: 2000; x_tolerance: 1
R12 = 001551: Thick-film resistor; Partnumber: 001551; Manufacturer: Vishay; ValueFloat: 34000; Tolerance (%): 1; Description 2: SM-0402, 1%, 1/16W
R13 = 001035: Thick-film resistor; Partnumber: 001035; Manufacturer: Vishay; ValueFloat: 49900; Tolerance (%): 1; Description 2: SM-0402, 1%, 1/16W

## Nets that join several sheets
+1.8VDD: Top (TP7.1), MC1 (C1.2 J3.2 MC1.177 MC1.179), Transceiver-M2 (6 pins)
+3.3V_M.2: Power (7 pins), Transceiver-M2 (27 pins)
+3.3V_QSFP: Transceiver-QSFP (31 pins), Power (7 pins)
+3.3V_SZG: MC2 (J4.40 J5.40), MC1 (J1.40 J2.40), Power (7 pins), MC3-Transceiver (J8.40 J23.40)
+3.3VDD: Top (TP4.1), MC1 (7 pins), Power (R30.2)
+5V_SZG: MC2 (J4.2 J5.2), MC1 (J1.2 J2.2), Power (7 pins), MC3-Transceiver (J8.2 J23.2)
+VDCIN: Top (TP2.1), MC1 (8 pins), Power (17 pins)
DGND: Top (TP10.1 TP13.1 TP15.1), Transceiver-QSFP (61 pins), MC2 (45 pins), MC1 (39 pins), Power (51 pins), Transceiver-M2 (41 pins), MC3-Transceiver (27 pins)
VCCBATT: Top (TP12.1), MC2 (MC2.6)
VIO1: Top (TP1.1), MC1 (J1.39 J2.39 MC1.174 MC1.176), MC3-Transceiver (J8.39 J23.39)
VIO2: Top (TP3.1), Transceiver-QSFP (15 pins), MC2 (J4.39 J5.39 MC2.2 MC2.4), Transceiver-M2 (10 pins)
VREF1: Top (TP6.1), MC1 (MC1.178)
VREF2: Top (TP9.1), MC2 (MC2.1)
100MHZ _REFCLK_P: Transceiver-M2 (U2.16), MC3-Transceiver (MC3.85 R11.2)
100MHZ_REFCLK_N: Transceiver-M2 (U2.15), MC3-Transceiver (MC3.87 R11.1)
I2C_SCL: MC2 (J4.1 J5.1), MC1 (J1.1 J2.1 MC1.12 U1.6), Power (U3.43), MC3-Transceiver (J8.1 J23.1)
I2C_SDA: MC2 (J4.3 J5.3), MC1 (J1.3 J2.3 MC1.10 U1.5), Power (U3.42), MC3-Transceiver (J8.3 J23.3)
M2_ALERT_B: MC2 (MC2.62), Transceiver-M2 (R34.1 U4.4)
M2_CLKREQ_B: MC2 (MC2.63), Transceiver-M2 (U5.2)
M2_DEVSLP: MC2 (MC2.59), Transceiver-M2 (U5.4)
M2_LED_1_B: MC2 (MC2.60), Transceiver-M2 (U5.5)
M2_PEDET: MC2 (MC2.64), Transceiver-M2 (U12.3)
M2_PER_N0: Transceiver-M2 (J32.41), MC3-Transceiver (MC3.83)
M2_PER_N1: Transceiver-M2 (J32.29), MC3-Transceiver (MC3.79)
M2_PER_N2: Transceiver-M2 (J32.17), MC3-Transceiver (MC3.75)
M2_PER_N3: Transceiver-M2 (J32.5), MC3-Transceiver (MC3.71)
M2_PER_P0: Transceiver-M2 (J32.43), MC3-Transceiver (MC3.81)
M2_PER_P1: Transceiver-M2 (J32.31), MC3-Transceiver (MC3.77)
M2_PER_P2: Transceiver-M2 (J32.19), MC3-Transceiver (MC3.73)
M2_PER_P3: Transceiver-M2 (J32.7), MC3-Transceiver (MC3.69)
M2_PERST_B: MC2 (MC2.61), Transceiver-M2 (U5.3)
M2_PET_N0: Transceiver-M2 (C83.1), MC3-Transceiver (MC3.84)
M2_PET_N1: Transceiver-M2 (C81.1), MC3-Transceiver (MC3.80)
M2_PET_N2: Transceiver-M2 (C79.1), MC3-Transceiver (MC3.76)
M2_PET_N3: Transceiver-M2 (C77.1), MC3-Transceiver (MC3.72)
M2_PET_P0: Transceiver-M2 (C84.1), MC3-Transceiver (MC3.82)
M2_PET_P1: Transceiver-M2 (C82.1), MC3-Transceiver (MC3.78)
M2_PET_P2: Transceiver-M2 (C80.1), MC3-Transceiver (MC3.74)
M2_PET_P3: Transceiver-M2 (C78.1), MC3-Transceiver (MC3.70)
M2_PEWAKE_B: MC2 (MC2.65), Transceiver-M2 (U12.4)
M2_SMB_CLK: MC2 (MC2.57), Transceiver-M2 (R32.1 U4.2)
M2_SMB_DATA: MC2 (MC2.55), Transceiver-M2 (R33.1 U4.3)
M2_SUSCLK: MC2 (MC2.66), Transceiver-M2 (U12.2)
M2_THREESTATE_N_IO: MC2 (MC2.177), Transceiver-M2 (R65.1 R66.2)
PORTE_C2P_CLKN: MC1 (MC1.135), MC3-Transceiver (J23.36)
PORTE_C2P_CLKP: MC1 (MC1.133), MC3-Transceiver (J23.34)
PORTE_P2C_CLKN: MC1 (MC1.142), MC3-Transceiver (J23.35)
PORTE_P2C_CLKP: MC1 (MC1.140), MC3-Transceiver (J23.33)
PORTE_S0: MC1 (MC1.122), MC3-Transceiver (J23.14)
PORTE_S1: MC1 (MC1.124), MC3-Transceiver (J23.16)
PORTE_S2: MC1 (MC1.126), MC3-Transceiver (J23.17)
PORTE_S3: MC1 (MC1.128), MC3-Transceiver (J23.18)
PORTE_S4: MC1 (MC1.130), MC3-Transceiver (J23.19)
PORTE_S5: MC1 (MC1.121), MC3-Transceiver (J23.20)
PORTE_S6: MC1 (MC1.123), MC3-Transceiver (J23.21)
PORTE_S7: MC1 (MC1.125), MC3-Transceiver (J23.22)
PORTE_S8: MC1 (MC1.127), MC3-Transceiver (J23.23)
PORTE_S9: MC1 (MC1.129), MC3-Transceiver (J23.24)
PORTF_C2P_CLKN: MC1 (MC1.136), MC3-Transceiver (J8.36)
PORTF_C2P_CLKP: MC1 (MC1.134), MC3-Transceiver (J8.34)
PORTF_P2C_CLKN: MC1 (MC1.146), MC3-Transceiver (J8.35)
PORTF_P2C_CLKP: MC1 (MC1.144), MC3-Transceiver (J8.33)
PORTF_S0: MC1 (MC1.152), MC3-Transceiver (J8.14)
PORTF_S1: MC1 (MC1.154), MC3-Transceiver (J8.16)
PORTF_S2: MC1 (MC1.156), MC3-Transceiver (J8.17)
PORTF_S3: MC1 (MC1.158), MC3-Transceiver (J8.18)
PORTF_S4: MC1 (MC1.160), MC3-Transceiver (J8.19)
PORTF_S5: MC1 (MC1.151), MC3-Transceiver (J8.20)
PORTF_S6: MC1 (MC1.153), MC3-Transceiver (J8.21)
PORTF_S7: MC1 (MC1.155), MC3-Transceiver (J8.22)
PORTF_S8: MC1 (MC1.157), MC3-Transceiver (J8.23)
PORTF_S9: MC1 (MC1.159), MC3-Transceiver (J8.24)
QSFP_1_INT_B: Transceiver-QSFP (U7.3), MC2 (MC2.129)
QSFP_1_LP_MODE: Transceiver-QSFP (U8.5), MC2 (MC2.125)
QSFP_1_MODPRS_B: Transceiver-QSFP (U8.2), MC2 (MC2.126)
QSFP_1_MODSEL_B: Transceiver-QSFP (U8.4), MC2 (MC2.122)
QSFP_1_RESET_B: Transceiver-QSFP (U8.3), MC2 (MC2.124)
QSFP_1_RX1N: Transceiver-QSFP (J30.18), MC3-Transceiver (MC3.51)
QSFP_1_RX1P: Transceiver-QSFP (J30.17), MC3-Transceiver (MC3.49)
QSFP_1_RX2N: Transceiver-QSFP (J30.21), MC3-Transceiver (MC3.47)
QSFP_1_RX2P: Transceiver-QSFP (J30.22), MC3-Transceiver (MC3.45)
QSFP_1_RX3N: Transceiver-QSFP (J30.15), MC3-Transceiver (MC3.43)
QSFP_1_RX3P: Transceiver-QSFP (J30.14), MC3-Transceiver (MC3.41)
QSFP_1_RX4N: Transceiver-QSFP (J30.24), MC3-Transceiver (MC3.39)
QSFP_1_RX4P: Transceiver-QSFP (J30.25), MC3-Transceiver (MC3.37)
QSFP_1_SCL: Transceiver-QSFP (R49.1 U9.4), MC2 (MC2.123)
QSFP_1_SDA: Transceiver-QSFP (R48.1 U9.5), MC2 (MC2.121)
QSFP_1_TX1N: Transceiver-QSFP (J30.37), MC3-Transceiver (MC3.52)
QSFP_1_TX1P: Transceiver-QSFP (J30.36), MC3-Transceiver (MC3.50)
QSFP_1_TX2N: Transceiver-QSFP (J30.2), MC3-Transceiver (MC3.48)
QSFP_1_TX2P: Transceiver-QSFP (J30.3), MC3-Transceiver (MC3.46)
QSFP_1_TX3N: Transceiver-QSFP (J30.34), MC3-Transceiver (MC3.44)
QSFP_1_TX3P: Transceiver-QSFP (J30.33), MC3-Transceiver (MC3.42)
QSFP_1_TX4N: Transceiver-QSFP (J30.5), MC3-Transceiver (MC3.40)
QSFP_1_TX4P: Transceiver-QSFP (J30.6), MC3-Transceiver (MC3.38)
QSFP_2_INT_B: Transceiver-QSFP (U10.3), MC2 (MC2.127)
QSFP_2_LP_MODE: Transceiver-QSFP (U11.5), MC2 (MC2.128)
QSFP_2_MODPRS_B: Transceiver-QSFP (U11.2), MC2 (MC2.134)
QSFP_2_MODSEL_B: Transceiver-QSFP (U11.4), MC2 (MC2.130)
QSFP_2_RESET_B: Transceiver-QSFP (U11.3), MC2 (MC2.132)
QSFP_2_RX1N: Transceiver-QSFP (J31.18), MC3-Transceiver (MC3.35)
QSFP_2_RX1P: Transceiver-QSFP (J31.17), MC3-Transceiver (MC3.33)
QSFP_2_RX2N: Transceiver-QSFP (J31.21), MC3-Transceiver (MC3.31)
QSFP_2_RX2P: Transceiver-QSFP (J31.22), MC3-Transceiver (MC3.29)
QSFP_2_RX3N: Transceiver-QSFP (J31.15), MC3-Transceiver (MC3.27)
QSFP_2_RX3P: Transceiver-QSFP (J31.14), MC3-Transceiver (MC3.25)
QSFP_2_RX4N: Transceiver-QSFP (J31.24), MC3-Transceiver (MC3.23)
QSFP_2_RX4P: Transceiver-QSFP (J31.25), MC3-Transceiver (MC3.21)
QSFP_2_SCL: Transceiver-QSFP (R50.1 U9.2), MC2 (MC2.131)
QSFP_2_SDA: Transceiver-QSFP (R51.1 U9.3), MC2 (MC2.133)
QSFP_2_TX1N: Transceiver-QSFP (J31.37), MC3-Transceiver (MC3.36)
QSFP_2_TX1P: Transceiver-QSFP (J31.36), MC3-Transceiver (MC3.34)
QSFP_2_TX2N: Transceiver-QSFP (J31.2), MC3-Transceiver (MC3.32)
QSFP_2_TX2P: Transceiver-QSFP (J31.3), MC3-Transceiver (MC3.30)
QSFP_2_TX3N: Transceiver-QSFP (J31.34), MC3-Transceiver (MC3.28)
QSFP_2_TX3P: Transceiver-QSFP (J31.33), MC3-Transceiver (MC3.26)
QSFP_2_TX4N: Transceiver-QSFP (J31.5), MC3-Transceiver (MC3.24)
QSFP_2_TX4P: Transceiver-QSFP (J31.6), MC3-Transceiver (MC3.22)
QSFP_THREESTATE_N_IO: Transceiver-QSFP (R62.1 R63.2), MC2 (MC2.179)

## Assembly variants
Default: not fitted MC1A MC1B MC2A MC2B MC2C MC2D R4 R5 R6 R11 R15 R38 R39 R41 R54 R55 R56 R57 R62 R63 R65 R66 SO1 SO2 SO3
